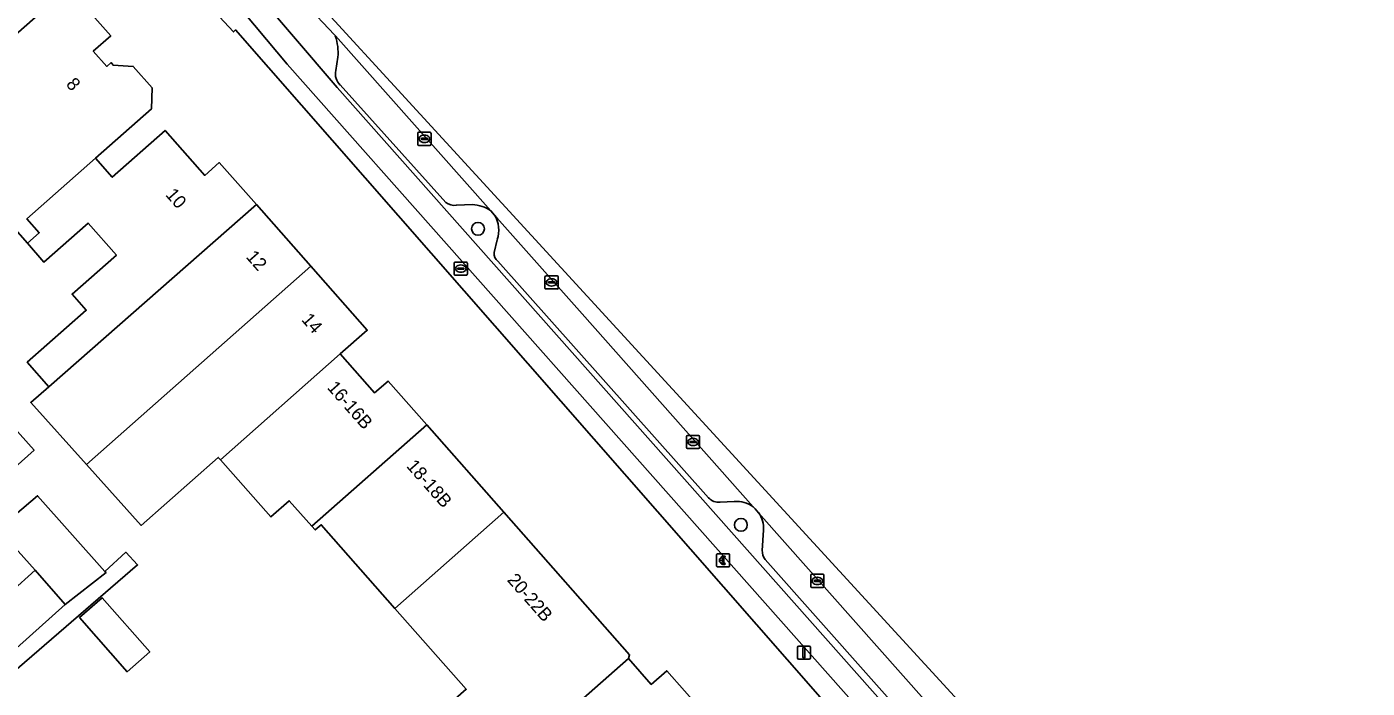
# Model space of a CAD drawing. Extents: x 159960 to 160866, y 382700 to 383354.
# Drawn here: x 160677.4 to 160779.5, y 383044.8 to 383095.2 of the extents above; entities that cross this region are included whole.
import ezdxf

# ---------------------------------------------------------------- set-up
doc = ezdxf.new("R2010")
doc.units = 0
for name, color, linetype in [('IMGEO_Berm_open', 7, 'Continuous'), ('IMGEO_Betaalautomaat', 7, 'Continuous'), ('IMGEO_Boom', 7, 'Continuous'), ('IMGEO_Brandkraan', 7, 'Continuous'), ('IMGEO_Erf', 7, 'Continuous'), ('IMGEO_Fietspad_gesloten', 7, 'Continuous'), ('IMGEO_Kolk', 7, 'Continuous'), ('IMGEO_Lichtmast', 7, 'Continuous'), ('IMGEO_Pand', 7, 'Continuous'), ('IMGEO_Pand_nummerreeks', 7, 'Continuous'), ('IMGEO_Parkeervlak_open', 7, 'Continuous'), ('IMGEO_Rijbaan_lokaal_gesloten', 7, 'Continuous'), ('IMGEO_Voetpad_open', 7, 'Continuous')]:
    doc.layers.add(name, color=color, linetype=linetype)

msp = doc.modelspace()

# ---------------------------------------------------------------- linework, layer by layer
at = {"layer": 'IMGEO_Berm_open'}
for points in [[(160700.88, 383094.51), (160700.8, 383094.59), (160698.59, 383096.92), (160695.7, 383099.8), (160694.16, 383101.34), (160689.09, 383106.24), (160687.38, 383107.89), (160684.6, 383110.79), (160683.97, 383110.17), (160686.7, 383107.39), (160688.82, 383104.99), (160694.35, 383098.36), (160701.02, 383090.57), (160751.34, 383033.87), (160762.2, 383021.76), (160762.42, 383021.96), (160761.59, 383022.89), (160761.75, 383023.03), (160753.73, 383031.94)], [(160700.91, 383091.87), (160701.07, 383092.88)], [(160709.29, 383081.83), (160701.25, 383090.77)], [(160711.31, 383081.66), (160710.09, 383081.62)], [(160713, 383080.86), (160712.71, 383081.19)], [(160712.96, 383078.01), (160713.21, 383078.99)], [(160729.3, 383059.34), (160713.25, 383077.36)], [(160731.26, 383059.05), (160730.19, 383059.01)], [(160733.11, 383058.2), (160732.84, 383058.51), (160732.7, 383058.66)], [(160733.38, 383055.34), (160733.49, 383056.87)], [(160749.55, 383036.7), (160733.61, 383054.63)]]:
    msp.add_lwpolyline(points, dxfattribs=at)
for centre, radius, start, end in [((160697.11, 383093.24), 3.97, 354.8783, 18.7046), ((160702.04, 383091.61), 1.16, 167.3239, 227.0641), ((160709.91, 383082.6), 0.996, 230.9453, 280.1443), ((160711.21, 383079.02), 2.64, 55.2751, 87.7322), ((160711.05, 383079.7), 2.27, 341.858, 30.9032), ((160713.65, 383077.92), 0.688, 172.2815, 234.6644), ((160730.1, 383060.15), 1.15, 225.2701, 274.3633), ((160731.41, 383056.75), 2.31, 55.9561, 93.5472), ((160731.48, 383057.03), 2.01, 355.533, 35.949), ((160734.68, 383055.36), 1.3, 180.6022, 214.042)]:
    msp.add_arc(centre, radius, start, end, dxfattribs=at)
at = {"layer": 'IMGEO_Betaalautomaat'}
for p, q in [((160729.9, 383054.16), (160729.9, 383055)), ((160729.9, 383055), (160729.9, 383054.16)), ((160729.98, 383055.08), (160730.82, 383055.08)), ((160730.82, 383055.08), (160729.98, 383055.08)), ((160730.19, 383054.55), (160730.19, 383054.61)), ((160730.31, 383054.61), (160730.31, 383054.55)), ((160730.57, 383054.89), (160730.55, 383054.79)), ((160730.9, 383055.01), (160730.9, 383054.17)), ((160730.9, 383054.17), (160730.9, 383055.01)), ((160730.83, 383054.08), (160729.99, 383054.08)), ((160729.99, 383054.08), (160730.83, 383054.08)), ((160730.55, 383054.38), (160730.57, 383054.29))]:
    msp.add_line(p, q, dxfattribs=at)
for points in [[(160730.19, 383054.61), (160730.12, 383054.61), (160730.12, 383054.68), (160730.2, 383054.68)], [(160730.19, 383054.48), (160730.12, 383054.48), (160730.12, 383054.55), (160730.19, 383054.55)], [(160730.32, 383054.68), (160730.47, 383054.68), (160730.47, 383054.61), (160730.31, 383054.61)], [(160730.31, 383054.55), (160730.47, 383054.55), (160730.47, 383054.48), (160730.32, 383054.48)]]:
    msp.add_lwpolyline(points, dxfattribs=at)
for centre, radius, start, end in [((160729.98, 383055), 0.0779, 92.4484, 184.2845), ((160729.98, 383055), 0.0779, 92.4484, 184.2845), ((160730.48, 383054.61), 0.293, 73.014, 165.0139), ((160730.49, 383054.62), 0.179, 69.3236, 159.5683), ((160730.83, 383055), 0.0779, 2.4484, 94.2845), ((160730.83, 383055), 0.0779, 2.4484, 94.2845), ((160729.98, 383054.16), 0.0779, 182.4484, 274.2845), ((160729.98, 383054.16), 0.0779, 182.4484, 274.2845), ((160730.45, 383054.53), 0.267, 191.8096, 297.0389), ((160730.49, 383054.55), 0.179, 202.7625, 291.8693), ((160730.83, 383054.16), 0.0779, 272.4484, 4.2845), ((160730.83, 383054.16), 0.0779, 272.4484, 4.2845)]:
    msp.add_arc(centre, radius, start, end, dxfattribs=at)
at = {"layer": 'IMGEO_Boom'}
for centre in [(160711.74, 383079.82), (160731.76, 383057.28)]:
    msp.add_circle(centre, 0.489, dxfattribs=at)
at = {"layer": 'IMGEO_Brandkraan'}
for p, q in [((160709.93, 383076.36), (160709.93, 383077.21)), ((160710, 383077.29), (160710.86, 383077.29)), ((160710.42, 383077.07), (160710.44, 383077.07)), ((160710.93, 383077.21), (160710.93, 383076.36)), ((160710.86, 383076.29), (160710, 383076.29)), ((160710.19, 383076.78), (160710.19, 383076.79)), ((160710.23, 383076.83), (160710.63, 383076.83)), ((160710.62, 383076.74), (160710.23, 383076.74)), ((160710.44, 383076.51), (160710.41, 383076.51)), ((160710.67, 383076.79), (160710.67, 383076.78))]:
    msp.add_line(p, q, dxfattribs=at)
for points in [[(160709.93, 383076.36), (160709.93, 383077.21)], [(160710, 383077.29), (160710.86, 383077.29)], [(160710.93, 383077.21), (160710.93, 383076.36)], [(160710.86, 383076.29), (160710, 383076.29)]]:
    msp.add_lwpolyline(points, dxfattribs=at)
for centre, radius, start, end in [((160710, 383077.21), 0.0765, 91.552, 178.448), ((160710, 383077.21), 0.0765, 91.552, 178.448), ((160710.85, 383077.21), 0.0765, 1.552, 88.448), ((160710.85, 383077.21), 0.0765, 1.552, 88.448), ((160710, 383076.36), 0.0765, 181.552, 268.448), ((160710, 383076.36), 0.0765, 181.552, 268.448), ((160710.23, 383076.79), 0.0403, 85.8775, 175.7526), ((160710.22, 383076.78), 0.0366, 178.938, 274.7102), ((160710.63, 383076.79), 0.043, 264.8664, 352.4533), ((160710.63, 383076.79), 0.0386, 1.7309, 96.639), ((160710.85, 383076.36), 0.0765, 271.552, 358.448), ((160710.85, 383076.36), 0.0765, 271.552, 358.448)]:
    msp.add_arc(centre, radius, start, end, dxfattribs=at)
for centre, major_axis, ratio, start_param, end_param in [((160710.42, 383076.79), (-0.387, 0.002), 0.722429, 4.712389, 7.853982), ((160710.44, 383076.79), (-0.39, 0.002), 0.717154, 1.570796, 4.712389)]:
    msp.add_ellipse(centre, major_axis=major_axis, ratio=ratio, start_param=start_param, end_param=end_param, dxfattribs=at)
at = {"layer": 'IMGEO_Erf'}
for points in [[(160680.54, 383098.16), (160683.77, 383094.51), (160682.44, 383093.34), (160683.46, 383092.18), (160683.79, 383092.47), (160683.95, 383092.28), (160685.48, 383092.18), (160686.92, 383090.55), (160686.87, 383088.95), (160682.61, 383085.19), (160683.88, 383083.75), (160687.91, 383087.31), (160690.93, 383083.89), (160692.03, 383084.86), (160694.86, 383081.66), (160699, 383076.97), (160703.3, 383072.1), (160701.25, 383070.29), (160703.86, 383067.33), (160704.89, 383068.23), (160707.83, 383064.89), (160713.71, 383058.24), (160723.28, 383047.39), (160723.19, 383047.11), (160724.93, 383045.13), (160726.11, 383046.17), (160728.81, 383043.12)], [(160790.27, 382985.75), (160777.19, 383000), (160752.7, 383027.15), (160693.28, 383094.96), (160693.11, 383094.81), (160692.06, 383095.95)], [(160710.84, 383044.77), (160705.41, 383050.92), (160699.8, 383057.29), (160699.35, 383056.89), (160699.09, 383057.18), (160697.37, 383059.12), (160695.97, 383057.88), (160692.13, 383062.23), (160691.96, 383062.42), (160686.08, 383057.24), (160681.92, 383061.88), (160677.68, 383066.6), (160679.05, 383067.8), (160677.41, 383069.66), (160681.91, 383073.62), (160680.83, 383074.85), (160684.2, 383077.82), (160682.04, 383080.26), (160678.67, 383077.29), (160677.42, 383078.72), (160673.49, 383083.16)], [(160669.87, 383071.97), (160677.93, 383062.97), (160675.52, 383060.82)], [(160676.5, 383058.04), (160678.2, 383059.49), (160683.33, 383053.74), (160684.93, 383055.2), (160685.81, 383054.23), (160673.24, 383043.39)], [(160674.27, 383050.47), (160678.01, 383053.83), (160674.77, 383057.44)]]:
    msp.add_lwpolyline(points, dxfattribs=at)
msp.add_lwpolyline([(160685.02, 383046.1), (160681.39, 383050.22), (160683.11, 383051.73), (160686.74, 383047.61)], close=True, dxfattribs=at)
at = {"layer": 'IMGEO_Fietspad_gesloten'}
for points in [[(160701.02, 383090.57), (160694.35, 383098.36), (160688.82, 383104.99), (160686.7, 383107.39), (160683.97, 383110.17), (160682.46, 383108.7)], [(160685.48, 383106.17), (160688.29, 383103.01), (160697.2, 383092.36), (160750.51, 383032.26), (160767.85, 383012.95), (160798.38, 382979.55), (160798.29, 382979.47), (160798.97, 382978.75), (160800.31, 382979.98), (160799.66, 382980.63), (160768.17, 383015.1), (160767.49, 383015.88)], [(160762.88, 383021.04), (160762.2, 383021.76), (160751.34, 383033.87), (160701.02, 383090.57)]]:
    msp.add_lwpolyline(points, dxfattribs=at)
at = {"layer": 'IMGEO_Kolk'}
for p, q in [((160707.16, 383086.24), (160707.16, 383087.1)), ((160707.23, 383087.17), (160708.08, 383087.17)), ((160707.41, 383086.66), (160707.41, 383086.68)), ((160707.85, 383086.63), (160707.45, 383086.63)), ((160707.46, 383086.71), (160707.86, 383086.71)), ((160707.64, 383086.95), (160707.67, 383086.95)), ((160707.67, 383086.39), (160707.64, 383086.39)), ((160707.9, 383086.68), (160707.9, 383086.66)), ((160708.16, 383087.1), (160708.16, 383086.24)), ((160708.08, 383086.17), (160707.23, 383086.17)), ((160716.84, 383075.31), (160716.84, 383076.17)), ((160716.92, 383076.24), (160717.77, 383076.24)), ((160717.33, 383076.02), (160717.36, 383076.02)), ((160717.84, 383076.17), (160717.84, 383075.31)), ((160717.77, 383075.24), (160716.92, 383075.24)), ((160717.1, 383075.73), (160717.1, 383075.75)), ((160717.14, 383075.78), (160717.54, 383075.78)), ((160717.54, 383075.7), (160717.14, 383075.7)), ((160717.35, 383075.46), (160717.33, 383075.46)), ((160717.59, 383075.75), (160717.59, 383075.73)), ((160727.62, 383063.16), (160727.62, 383064.01)), ((160727.69, 383064.09), (160728.55, 383064.09)), ((160728.11, 383063.87), (160728.13, 383063.87)), ((160728.62, 383064.01), (160728.62, 383063.16)), ((160728.55, 383063.09), (160727.69, 383063.09)), ((160727.88, 383063.58), (160727.88, 383063.59)), ((160727.92, 383063.63), (160728.32, 383063.63)), ((160728.32, 383063.54), (160727.92, 383063.54)), ((160728.13, 383063.31), (160728.1, 383063.31)), ((160728.36, 383063.59), (160728.36, 383063.58)), ((160737.09, 383052.59), (160737.09, 383053.44)), ((160737.16, 383053.52), (160738.01, 383053.52)), ((160738.01, 383052.51), (160737.16, 383052.51)), ((160737.34, 383053.01), (160737.34, 383053.02)), ((160737.78, 383052.97), (160737.38, 383052.97)), ((160737.39, 383053.06), (160737.79, 383053.06)), ((160737.57, 383053.29), (160737.6, 383053.29)), ((160737.6, 383052.74), (160737.57, 383052.74)), ((160737.83, 383053.02), (160737.83, 383053.01)), ((160738.09, 383053.44), (160738.09, 383052.59))]:
    msp.add_line(p, q, dxfattribs=at)
for points in [[(160707.16, 383086.24), (160707.16, 383087.1)], [(160707.23, 383087.17), (160708.08, 383087.17)], [(160708.16, 383087.1), (160708.16, 383086.24)], [(160708.08, 383086.17), (160707.23, 383086.17)], [(160716.84, 383075.31), (160716.84, 383076.17)], [(160716.92, 383076.24), (160717.77, 383076.24)], [(160717.84, 383076.17), (160717.84, 383075.31)], [(160717.77, 383075.24), (160716.92, 383075.24)], [(160727.62, 383063.16), (160727.62, 383064.01)], [(160727.69, 383064.09), (160728.55, 383064.09)], [(160728.62, 383064.01), (160728.62, 383063.16)], [(160728.55, 383063.09), (160727.69, 383063.09)], [(160737.09, 383052.59), (160737.09, 383053.44)], [(160737.16, 383053.52), (160738.01, 383053.52)], [(160738.01, 383052.51), (160737.16, 383052.51)], [(160738.09, 383053.44), (160738.09, 383052.59)]]:
    msp.add_lwpolyline(points, dxfattribs=at)
for centre, radius, start, end in [((160707.23, 383087.1), 0.0765, 91.552, 178.448), ((160707.23, 383087.1), 0.0765, 91.552, 178.448), ((160707.23, 383086.25), 0.0765, 181.552, 268.448), ((160707.23, 383086.25), 0.0765, 181.552, 268.448), ((160707.46, 383086.67), 0.0403, 85.8775, 175.7526), ((160707.45, 383086.66), 0.0366, 178.938, 274.7102), ((160707.86, 383086.67), 0.043, 264.8664, 352.4533), ((160707.86, 383086.68), 0.0386, 1.7309, 96.639), ((160708.08, 383087.1), 0.0765, 1.552, 88.448), ((160708.08, 383087.1), 0.0765, 1.552, 88.448), ((160708.08, 383086.25), 0.0765, 271.552, 358.448), ((160708.08, 383086.25), 0.0765, 271.552, 358.448), ((160716.92, 383076.16), 0.0765, 91.552, 178.448), ((160716.92, 383076.16), 0.0765, 91.552, 178.448), ((160717.77, 383076.16), 0.0765, 1.552, 88.448), ((160717.77, 383076.16), 0.0765, 1.552, 88.448), ((160716.92, 383075.31), 0.0765, 181.552, 268.448), ((160716.92, 383075.31), 0.0765, 181.552, 268.448), ((160717.14, 383075.74), 0.0403, 85.8775, 175.7526), ((160717.14, 383075.73), 0.0366, 178.938, 274.7102), ((160717.55, 383075.74), 0.0386, 1.7309, 96.639), ((160717.54, 383075.74), 0.043, 264.8664, 352.4533), ((160717.77, 383075.31), 0.0765, 271.552, 358.448), ((160717.77, 383075.31), 0.0765, 271.552, 358.448), ((160727.7, 383064.01), 0.0765, 91.552, 178.448), ((160727.7, 383064.01), 0.0765, 91.552, 178.448), ((160728.54, 383064.01), 0.0765, 1.552, 88.448), ((160728.54, 383064.01), 0.0765, 1.552, 88.448), ((160727.7, 383063.16), 0.0765, 181.552, 268.448), ((160727.7, 383063.16), 0.0765, 181.552, 268.448), ((160727.92, 383063.59), 0.0403, 85.8775, 175.7526), ((160727.91, 383063.58), 0.0366, 178.938, 274.7102), ((160728.32, 383063.59), 0.0386, 1.7309, 96.639), ((160728.32, 383063.59), 0.043, 264.8664, 352.4533), ((160728.54, 383063.16), 0.0765, 271.552, 358.448), ((160728.54, 383063.16), 0.0765, 271.552, 358.448), ((160737.16, 383053.44), 0.0765, 91.552, 178.448), ((160737.16, 383053.44), 0.0765, 91.552, 178.448), ((160737.16, 383052.59), 0.0765, 181.552, 268.448), ((160737.16, 383052.59), 0.0765, 181.552, 268.448), ((160737.39, 383053.02), 0.0403, 85.8775, 175.7526), ((160737.38, 383053.01), 0.0366, 178.938, 274.7102), ((160737.79, 383053.01), 0.043, 264.8664, 352.4533), ((160737.79, 383053.02), 0.0386, 1.7309, 96.639), ((160738.01, 383053.44), 0.0765, 1.552, 88.448), ((160738.01, 383053.44), 0.0765, 1.552, 88.448), ((160738.01, 383052.59), 0.0765, 271.552, 358.448), ((160738.01, 383052.59), 0.0765, 271.552, 358.448)]:
    msp.add_arc(centre, radius, start, end, dxfattribs=at)
for centre, major_axis, ratio, start_param, end_param in [((160707.64, 383086.67), (-0.387, 0.002), 0.722429, 4.712389, 7.853982), ((160707.67, 383086.67), (-0.39, 0.002), 0.717154, 1.570796, 4.712389), ((160717.33, 383075.74), (-0.387, 0.002), 0.722429, 4.712389, 7.853982), ((160717.35, 383075.74), (-0.39, 0.002), 0.717154, 1.570796, 4.712389), ((160728.11, 383063.59), (-0.387, 0.002), 0.722429, 4.712389, 7.853982), ((160728.13, 383063.59), (-0.39, 0.002), 0.717154, 1.570796, 4.712389), ((160737.57, 383053.01), (-0.387, 0.002), 0.722429, 4.712389, 7.853982), ((160737.6, 383053.01), (-0.39, 0.002), 0.717154, 1.570796, 4.712389)]:
    msp.add_ellipse(centre, major_axis=major_axis, ratio=ratio, start_param=start_param, end_param=end_param, dxfattribs=at)
at = {"layer": 'IMGEO_Lichtmast'}
for p, q in [((160736.07, 383047.15), (160736.07, 383047.95)), ((160736.07, 383047.95), (160736.07, 383047.15)), ((160736.17, 383048.05), (160736.96, 383048.05)), ((160736.96, 383048.05), (160736.17, 383048.05)), ((160737.06, 383047.95), (160737.06, 383047.15)), ((160737.06, 383047.15), (160737.06, 383047.95)), ((160736.96, 383047.05), (160736.17, 383047.05)), ((160736.17, 383047.05), (160736.96, 383047.05))]:
    msp.add_line(p, q, dxfattribs=at)
msp.add_lwpolyline([(160736.49, 383047.93), (160736.64, 383047.93), (160736.64, 383047.18), (160736.49, 383047.18), (160736.49, 383047.93)], dxfattribs=at)
for centre, start, end in [((160736.17, 383047.95), 90, 180), ((160736.17, 383047.95), 90, 180), ((160736.96, 383047.95), 0, 90), ((160736.96, 383047.95), 360, 90), ((160736.17, 383047.15), 180, 270), ((160736.17, 383047.15), 180, 270), ((160736.96, 383047.15), 270, 0), ((160736.96, 383047.15), 270, 0)]:
    msp.add_arc(centre, 0.1, start, end, dxfattribs=at)
at = {"layer": 'IMGEO_Pand'}
for points in [[(160682.61, 383085.19), (160686.87, 383088.95), (160686.92, 383090.55), (160685.48, 383092.18), (160683.95, 383092.28), (160683.79, 383092.47), (160683.46, 383092.18), (160682.44, 383093.34), (160683.77, 383094.51), (160680.54, 383098.16), (160669.54, 383088.46), (160672.49, 383085.11), (160673.38, 383085.89), (160674.78, 383084.3), (160673.49, 383083.16), (160677.42, 383078.72), (160678.33, 383079.52), (160677.39, 383080.59)], [(160682.61, 383085.19), (160677.39, 383080.59), (160678.33, 383079.52), (160677.42, 383078.72), (160678.67, 383077.29), (160682.04, 383080.26), (160684.2, 383077.82), (160680.83, 383074.85), (160681.91, 383073.62), (160677.41, 383069.66), (160679.05, 383067.8), (160694.86, 383081.66), (160692.03, 383084.86), (160690.93, 383083.89), (160687.91, 383087.31), (160683.88, 383083.75)], [(160681.92, 383061.88), (160699, 383076.97), (160694.86, 383081.66), (160679.05, 383067.8), (160677.68, 383066.6)], [(160681.92, 383061.88), (160686.08, 383057.24), (160691.96, 383062.42), (160692.13, 383062.23), (160701.25, 383070.29), (160703.3, 383072.1), (160699, 383076.97)], [(160677.93, 383062.97), (160669.87, 383071.97), (160666.41, 383068.88), (160667.34, 383067.84), (160666.29, 383066.9), (160674.77, 383057.44), (160678.01, 383053.83), (160680.31, 383051.22), (160683.41, 383053.65), (160683.33, 383053.74), (160678.2, 383059.49), (160676.5, 383058.04), (160675.56, 383058.9), (160676.49, 383059.74), (160675.52, 383060.82)], [(160707.83, 383064.89), (160704.89, 383068.23), (160703.86, 383067.33), (160701.25, 383070.29), (160692.13, 383062.23), (160695.97, 383057.88), (160697.37, 383059.12), (160699.09, 383057.18)], [(160699.09, 383057.18), (160699.35, 383056.89), (160699.8, 383057.29), (160705.41, 383050.92), (160713.71, 383058.24), (160707.83, 383064.89)], [(160723.19, 383047.11), (160723.28, 383047.39), (160713.71, 383058.24), (160705.41, 383050.92), (160710.84, 383044.77), (160707.92, 383042.2), (160709.14, 383040.81), (160709.49, 383041.12), (160710.14, 383040.38), (160709.81, 383040.09), (160712.16, 383037.39), (160712.51, 383037.7)], [(160678.01, 383053.83), (160674.27, 383050.47), (160676.59, 383047.88), (160680.31, 383051.22)], [(160681.39, 383050.22), (160685.02, 383046.1), (160686.74, 383047.61), (160683.11, 383051.73)], [(160728.81, 383043.12), (160726.11, 383046.17), (160724.93, 383045.13), (160723.19, 383047.11), (160712.51, 383037.7), (160712.16, 383037.39), (160713.84, 383035.46), (160714.21, 383035.78), (160714.84, 383036.34), (160717.58, 383033.22), (160720.05, 383035.4), (160721.3, 383036.5)]]:
    msp.add_lwpolyline(points, close=True, dxfattribs=at)
at = {"layer": 'IMGEO_Parkeervlak_open'}
for points in [[(160712.71, 383081.19), (160700.88, 383094.51)], [(160701.07, 383092.88), (160700.91, 383091.87)], [(160701.25, 383090.77), (160709.29, 383081.83)], [(160710.09, 383081.62), (160711.31, 383081.66)], [(160719.68, 383073.34), (160713.18, 383080.66), (160713, 383080.86)], [(160713.21, 383078.99), (160712.96, 383078.01)], [(160713.25, 383077.36), (160729.3, 383059.34)], [(160732.7, 383058.66), (160719.68, 383073.34)], [(160730.19, 383059.01), (160731.26, 383059.05)], [(160753.13, 383035.63), (160733.11, 383058.2)], [(160733.49, 383056.87), (160733.38, 383055.34)], [(160733.61, 383054.63), (160749.55, 383036.7)]]:
    msp.add_lwpolyline(points, dxfattribs=at)
for centre, radius, start, end in [((160697.11, 383093.24), 3.97, 354.8783, 18.7046), ((160702.04, 383091.61), 1.16, 167.3239, 227.0641), ((160709.91, 383082.6), 0.996, 230.9453, 280.1443), ((160711.21, 383079.02), 2.64, 55.2751, 87.7322), ((160711.05, 383079.7), 2.27, 341.858, 30.9032), ((160713.65, 383077.92), 0.688, 172.2815, 234.6644), ((160730.1, 383060.15), 1.15, 225.2701, 274.3633), ((160731.41, 383056.75), 2.31, 55.9561, 93.5472), ((160731.48, 383057.03), 2.01, 355.533, 35.949), ((160734.68, 383055.36), 1.3, 180.6022, 214.042)]:
    msp.add_arc(centre, radius, start, end, dxfattribs=at)
at = {"layer": 'IMGEO_Rijbaan_lokaal_gesloten'}
msp.add_lwpolyline([(160856.41, 382930.08), (160844.82, 382938.75), (160792.96, 382995.27), (160690.09, 383107.36), (160689.09, 383106.24), (160694.16, 383101.34), (160695.7, 383099.8), (160698.59, 383096.92), (160700.8, 383094.59), (160700.88, 383094.51), (160712.71, 383081.19), (160713, 383080.86), (160713.18, 383080.66), (160719.68, 383073.34), (160732.7, 383058.66), (160732.84, 383058.51), (160733.11, 383058.2), (160753.13, 383035.63), (160765.27, 383022.08), (160765.71, 383021.57), (160768.35, 383018.63), (160768.77, 383018.17), (160781.34, 383004.39), (160801.71, 382982.11)], dxfattribs=at)
at = {"layer": 'IMGEO_Voetpad_open'}
for points in [[(160680.2, 383109.39), (160682.94, 383106.47), (160690.08, 383098.11), (160692.06, 383095.95), (160693.11, 383094.81), (160693.28, 383094.96), (160752.7, 383027.15), (160777.19, 383000), (160790.27, 382985.75), (160790.19, 382984.79), (160790.89, 382984.56), (160791.86, 382984.26), (160795.23, 382980.57), (160804.56, 382970.34), (160805.23, 382969.7), (160808.48, 382966.14), (160814.65, 382959.32)], [(160813.79, 382962.52), (160806.08, 382971.01), (160805.54, 382970.52), (160800.11, 382976.39), (160800.67, 382976.94), (160798.97, 382978.75), (160798.29, 382979.47), (160798.38, 382979.55), (160767.85, 383012.95), (160750.51, 383032.26), (160697.2, 383092.36), (160688.29, 383103.01)]]:
    msp.add_lwpolyline(points, dxfattribs=at)
msp.add_lwpolyline([(160683.33, 383053.74), (160683.41, 383053.65), (160680.31, 383051.22), (160676.59, 383047.88), (160672.47, 383044.2), (160673.24, 383043.39), (160685.81, 383054.23), (160684.93, 383055.2)], close=True, dxfattribs=at)

# ---------------------------------------------------------------- texts
at = {"layer": 'IMGEO_Pand_nummerreeks'}
for s, rotation, p in [('8', 311.3925, (160680.31, 383090.79)), ('10', 311.4176, (160687.89, 383082.38)), ('12', 311.4192, (160694.02, 383077.65)), ('14', 311.4192, (160698.24, 383072.87)), ('16-16B', 311.4246, (160700.2, 383067.7)), ('18-18B', 311.5016, (160706.24, 383061.72)), ('20-22B', 311.4132, (160713.91, 383053.05))]:
    msp.add_text(s, height=1, rotation=rotation, dxfattribs=at).set_placement(p)

doc.saveas('drawing.dxf')
